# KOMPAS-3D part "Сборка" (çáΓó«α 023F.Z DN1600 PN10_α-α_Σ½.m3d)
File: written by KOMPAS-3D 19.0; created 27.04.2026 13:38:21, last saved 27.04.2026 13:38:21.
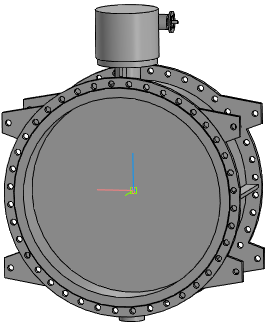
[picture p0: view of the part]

Document properties: Автор: Энергия; Полное имя файла: ..\..\Затвор 023F.Z DN200-DN1600_редуктор с входным фланцем\Затвор 023F.Z DN1600 PN10 + редуктор с входным фланцем.a3d

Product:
- Part/product: Сборка
    Масса: 4217.99

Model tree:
1. Операция без истории:1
